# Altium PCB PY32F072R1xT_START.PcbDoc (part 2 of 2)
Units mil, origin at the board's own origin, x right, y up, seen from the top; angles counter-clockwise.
Board outline 1771.65 x 3925.12 mil, 2 copper layers (Top Layer, Bottom Layer), stack 21 mil thick; 156 components, 167 nets, 616 pads, 288 vias.
Unrouted connection lines stored in the file: 5.
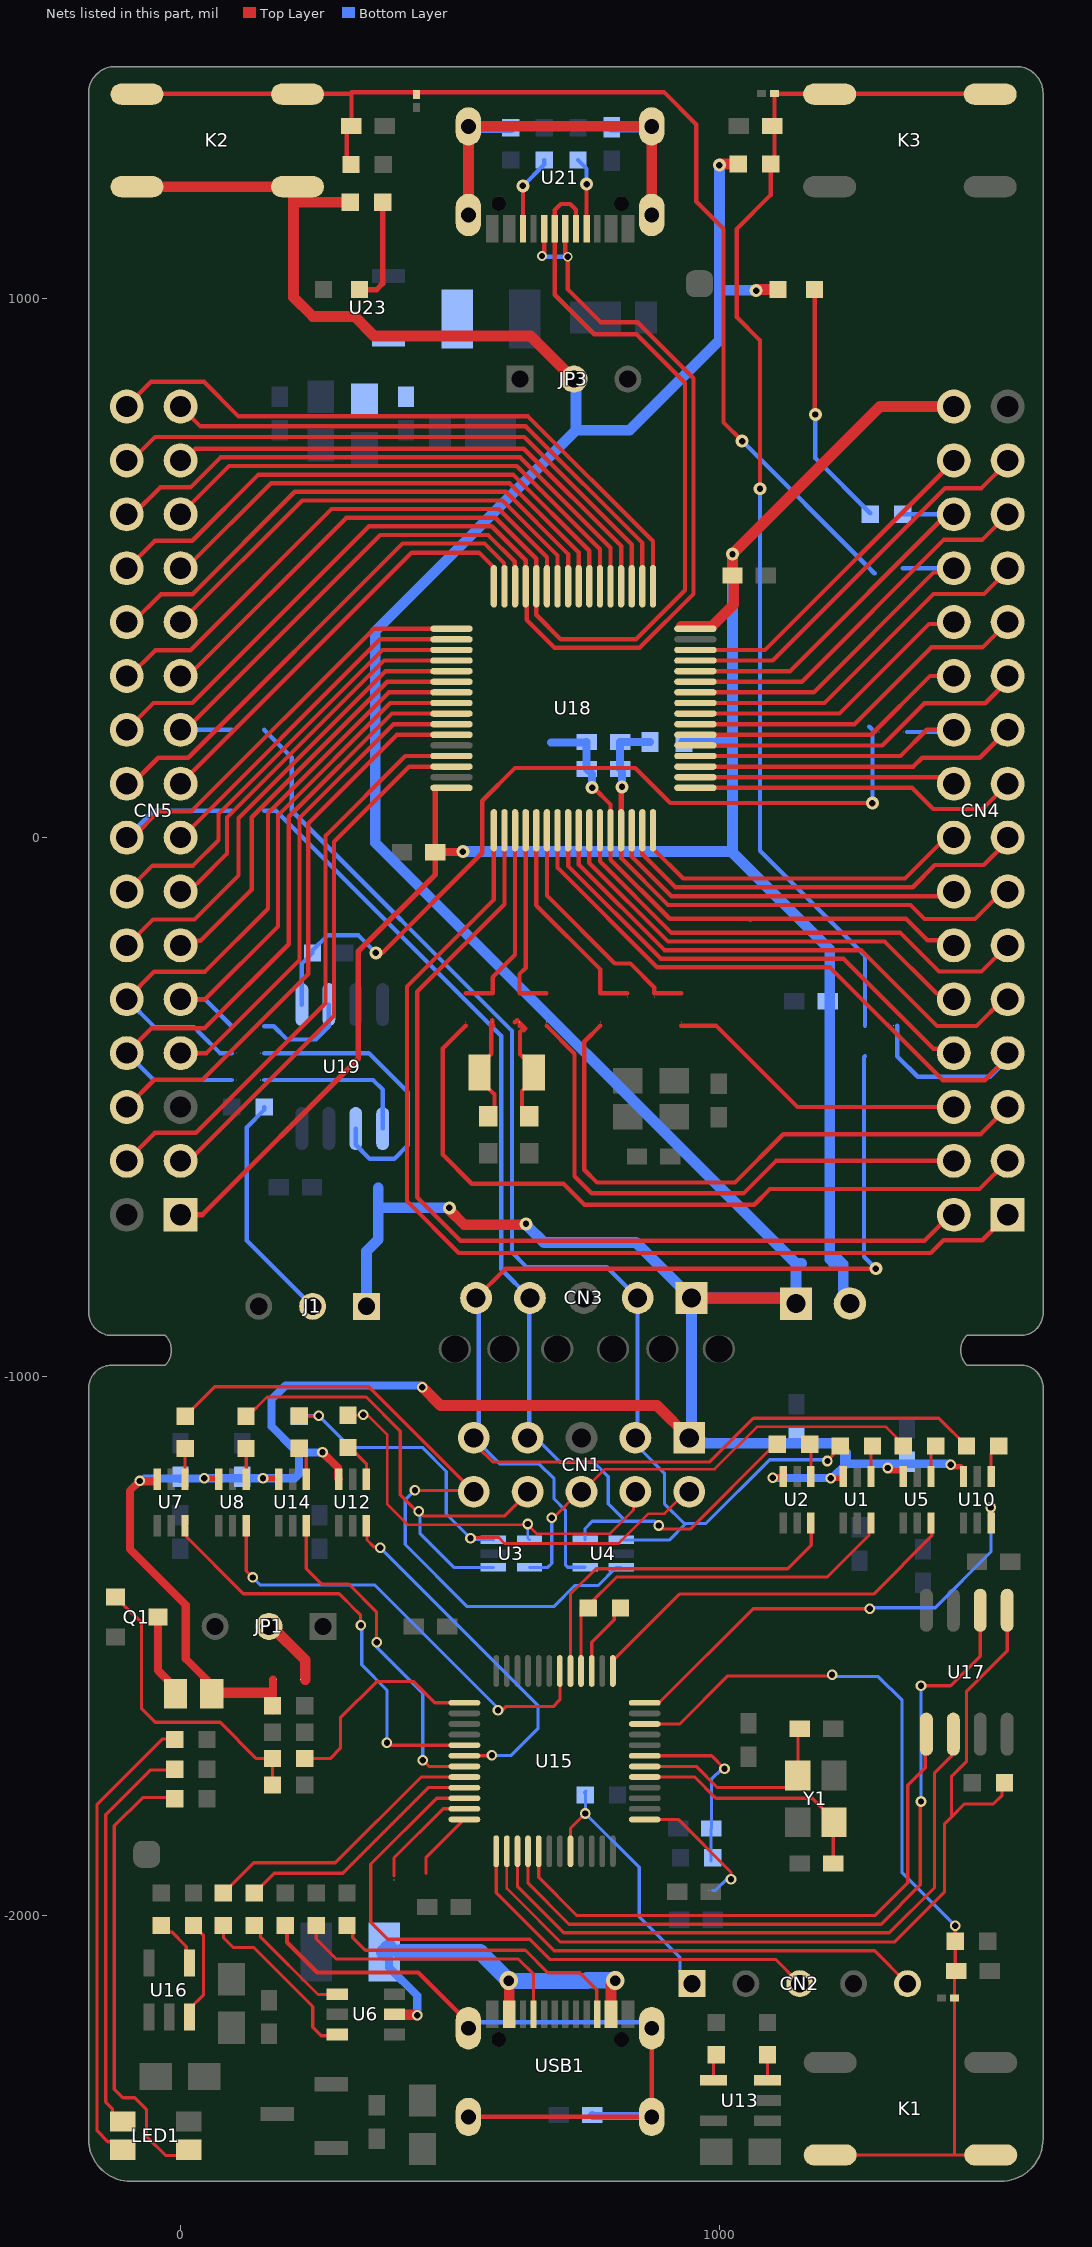
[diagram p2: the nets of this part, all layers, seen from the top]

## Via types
v1: diameter 24, hole 12, Top Layer to Bottom Layer, tented both sides, 117 vias
v2: diameter 19.68, hole 11.81, Top Layer to Bottom Layer, tented both sides, 109 vias
v3: diameter 19.68, hole 11.81, Top Layer to Bottom Layer, 41 vias
v4: diameter 35, hole 20, Top Layer to Bottom Layer, tented both sides, 15 vias
v5: diameter 17.72, hole 11.81, Top Layer to Bottom Layer, tented both sides, 2 vias
v6: diameter 30, hole 15, Top Layer to Bottom Layer, tented both sides, 2 vias
v7: diameter 40, hole 20, Top Layer to Bottom Layer, tented both sides, 2 vias

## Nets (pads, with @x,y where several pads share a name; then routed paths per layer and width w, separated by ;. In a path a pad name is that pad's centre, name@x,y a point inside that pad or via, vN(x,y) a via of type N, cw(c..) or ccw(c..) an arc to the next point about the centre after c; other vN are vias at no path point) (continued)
NetC28_1: C28.1 R42.2 Y3.2 | length 212.9
  Top Layer w8: C28.1@571,-517 582.56,-505.44 582.56,-476.54 554.81,-448.79 Y3.2@554.81,-436 554.81,-423.2 576.75,-401.25 576.75,-351 ; 575.84,-348.25 578.15,-338.54 578.15,-346.4 580.75,-349
NetC29_2: C29.2 R43.2 Y3.1 | length 231
  Top Layer w8: 620.24,-342.82 624.53,-338.53 ; 629,-349 629,-343 640.2,-354.2 636.56,-357.84 ; 636,-351 636,-354.49 629.97,-360.52 629.97,-401.84 634.65,-406.53 638.53,-406.53 646,-414 Y3.1@646,-442 ; C29.2@647,-517 633.5,-503.5 633.5,-470.49 655.2,-448.79 Y3.1@655.2,-436
NetC34_2: C34.2 K3.1 R51.2 R52.1 U20.1 | length 2260.3
  Top Layer w8: v1(1075.24,647.39) 1075.24,922.79 1032.01,966.01 1032.01,1129.47 1095,1192.45 1095,1247.12 R51.2@1095,1250.24 ; R51.2@1098.12,1247.12 1102.3,1251.3 U20.1@1102.3,1381 1102.95,1380.35 1501.9,1380.35 K3.1@1502.55,1379.7
  Bottom Layer w8: v1(1075.24,647.39) 1075.24,-24.52 1270,-219.28 1270,-349
NetC35_2: C35.2 K2.1 R53.1 R54.2 U22.1 | length 2245.4
  Top Layer w8: K2.1@-81,1379.7 -80.35,1380.35 217,1380.35 317,1380.35 C35.2@317,1321 ; R54.2@308.14,1251.87 308.14,1312.14 C35.2@317,1321 ; R54.2@316,1249.26 R54.2@328,1237.26 ; v1(1042.19,735.83) 1007.54,770.49 1007.54,1129.86 956.86,1180.53 956.86,1323.74 897.03,1383.57 317.28,1383.57 317,1383.29 C35.2@317,1321
  Bottom Layer w8: v1(1042.19,735.83) 1275.42,502.61 1276,502.61 1276,502 1287.39,490.61 1288,490.61
NetC38_2: C38.2 C39.2 FUSE2.2 U23.3
NetC40_2: C40.2 R7.1 USB1.1 USB1.2 USB1.3 USB1.4 | length 1406.9
  Top Layer w8: R7.1@194,-2019 197.29,-2022.29 197.29,-2050.13 253.64,-2106.48 440.97,-2106.48 534.12,-2199.63 USB1.1@534.12,-2209.71 ; USB1.3@534.12,-2374.27 USB1.4@874.28,-2374.27 USB1.2@874.28,-2209.71
  Bottom Layer w8: USB1.1@545.04,-2198.79 USB1.2@863.36,-2198.79
  Bottom Layer w15: C40.2@764,-2371 765.64,-2372.64 872.64,-2372.64 USB1.4@874.28,-2374.27
  Bottom Layer w20: USB1.1@534.12,-2209.71 USB1.1@545.04,-2198.79 ; USB1.2@863.36,-2198.79 USB1.2@874.28,-2209.71
NetC41_2: C41.2 R57.2 U21.1 U21.2 U21.3 U21.4 | length 832
  Top Layer w20: U21.2@534.12,1155.52 U21.4@534.12,1320.08 U21.3@874.28,1320.08 U21.1@874.28,1155.52 U21.1@874.28,1163.89
  Bottom Layer w20: U21.4@534.12,1320.08 536.7,1317.5 R57.2@612.5,1317.5 ; C41.2@800,1318.5 872.69,1318.5 U21.3@874.28,1320.08
NetJ1_2: J1.2 R41.1 | length 433.9
  Bottom Layer w8: R41.1@155,-500 155,-505.59 122.74,-537.85 122.74,-747.61 J1.2@245,-869.87
NetLED1_2: LED1.2 R8.1 | length 846.1
  Top Layer w6: R8.1@-11,-1784 -13.33,-1781.67 -70.67,-1781.67 -123,-1834 -123,-2323 -107.2,-2338.8 -85.14,-2338.8 -63.47,-2360.47 -63.47,-2409.84 -27.18,-2446.13 4.08,-2446.13 LED1.2@15.02,-2435.18
NetLED1_3: LED1.3 R5.1 | length 884.3
  Top Layer w6: LED1.3@-126.72,-2435.48 LED1.3@-112.02,-2450.18 ; LED1.3@-107.02,-2435.18 -121.72,-2420.48 -134.91,-2420.48 -155,-2400.39 -155,-1793.66 -34.41,-1673.07 -11.93,-1673.07 R5.1@-11,-1674
NetLED1_4: LED1.4 R4.1 | length 755.1
  Top Layer w6: LED1.4@-114.34,-2395.5 -126.64,-2383.19 -126.64,-2359.26 -139,-2346.91 -139,-1813.66 -55.61,-1730.27 -12.27,-1730.27 R4.1@-11,-1729
NetLED2_VDD*_1: LED2_VDD*.1 R59.1 | length 198.6
  Top Layer w10: LED2_VDD*.1@332,1017 364,1017 375,1028 R59.1@375,1179
NetLED3_PB2_2: LED3_PB2.2 R46.1 | length 460.1
  Top Layer w8: LED3_PB2.2@1176.06,1018.88 1177.06,1017.88 1177.06,788.95 v1@1178.04,787.97
  Bottom Layer w8: v1@1178.04,787.97 1178.04,703.9 R46.1@1280.06,601.88
  other v1: 1178.22,785.23
NetQ1_1: Q1.1 R18.1 R19.2 | length 559
  Top Layer w6: Q1.1@-121,-1409.2 -119.03,-1409.2 -107.28,-1420.94 -107.28,-1422.77 -72.54,-1457.51 -72.54,-1616.66 -47.14,-1642.06 73.45,-1642.06 140.61,-1709.22 R18.1@170.53,-1709.22 ; R19.2@170.52,-1758.12 R18.1@170.52,-1709.23
NetQ1_3: Q1.3 R14.1 | length 166.5
  Top Layer w6: Q1.3@-45.51,-1449.85 Q1.3@-42.26,-1446.6 ; R14.1@-9.46,-1589 R14.1@-9.46,-1583.09
  Top Layer w15: Q1.3@-42.26,-1446.6 -42.26,-1545.72 -9.46,-1578.51 R14.1@-9.46,-1589
NetR1_2: R1.2 USB1.A5 | length 530.2
  Top Layer w6: R1.2@251.49,-2019.01 251.49,-2044.18 288.51,-2081.21 626.58,-2081.21 655.13,-2109.75 USB1.A5@655.13,-2183.97
NetR2_1: R2.1 U1.4 | length 57.9
  Top Layer w6: U1.4@1281.23,-1185.69 1281.23,-1131.98 R2.1@1284.21,-1129
NetR3_1: R3.1 USB1.B5 | length 566
  Top Layer w6: R3.1@309,-2019 319.31,-2029.31 319.31,-2041.66 342.85,-2065.2 640.11,-2065.2 681.66,-2106.76 740.55,-2106.76 772.17,-2138.38 772.17,-2183.18 USB1.B5@773.1,-2184.11
NetR6_1: R6.1 U2.4 | length 57.8
  Top Layer w6: R6.1@1167.06,-1129 1169.8,-1131.73 U2.4@1169.8,-1185.69
NetR9_1: R9.1 U5.4 | length 60.3
  Top Layer w6: U5.4@1392.66,-1185.69 1392.66,-1137.7 R9.1@1401.35,-1129
NetR10_1: R10.1 U6.3 | length 332.9
  Top Layer w6: R10.1@79,-2019 79.77,-2019.77 79.77,-2042.31 97.41,-2059.95 135.8,-2059.95 245.24,-2169.39 245.24,-2208.13 260.63,-2223.52 288.74,-2223.52 U6.3@290.53,-2221.72
NetR11_1: R11.1 U6.1 | length 227.7
  Top Layer w6: R11.1@137.75,-2014 148.15,-2024.4 148.15,-2040.32 255,-2147.17 U6.1@300.97,-2147.17
NetR12_1: R12.1 U7.4 | length 59
  Top Layer w6: R12.1@2.55,-1134 8.14,-1139.59 U7.4@8.14,-1190.69
NetR13_1: R13.1 U8.4 | length 60.8
  Top Layer w6: R13.1@109.94,-1133.98 R13.1@119.82,-1143.86 ; U8.4@121.86,-1190.69 R13.1@121.86,-1143.88
NetR17_1: R17.1 U10.4 | length 62.7
  Top Layer w6: U10.4@1504.08,-1185.69 1504.08,-1143.41 R17.1@1518.49,-1129
NetR21_1: R21.1 U12.4 | length 75.3
  Top Layer w6: R21.1@310.63,-1131.89 314.62,-1131.89 344.71,-1161.97 U12.4@344.71,-1190.69
NetR23_2: R23.2 U13.4 | length 49.6
  Top Layer w6: U13.4@989,-2306.5 989,-2264 R23.2@994,-2259
NetR24_2: R24.2 U13.3 | length 47.5
  Top Layer w6: U13.3@1089,-2306.5 R24.2@1089,-2259
NetR25_1: R25.1 U14.4 | length 62.8
  Top Layer w6: R25.1@220.2,-1133.3 233.28,-1146.38 U14.4@233.28,-1190.69
NetR26_2: R26.2 U15.1 | length 256.3
  Top Layer w6: U15.1@861.32,-1822.27 923.18,-1822.27 1021.46,-1920.55 v3(1021.46,-1933.12)
  Bottom Layer w6: 987.34,-1954.17 992.61,-1954.17 1013.66,-1933.12 v3(1021.46,-1933.12)
NetR28_2: R28.2 U16.4 | length 96.1
  Top Layer w6: R28.2@-36,-2019 -24,-2031 -16.56,-2031 10.5,-2058.06 10.5,-2083 U16.4@16.5,-2089
NetR29_2: R29.2 U16.3 | length 188.5
  Top Layer w6: U16.3@16.5,-2189 16.5,-2174 42.56,-2147.94 42.56,-2038.32 36,-2031.76 36,-2031 R29.2@24,-2019
NetR30_1: R30.1 U15.36 | length 129.6
  Top Layer w6: 455.21,-1922.25 455.21,-1893.74 U15.36@526.68,-1822.27
NetR32_1: R32.1 U15.35 | length 201.4
  Top Layer w6: 395.96,-1926.6 395.96,-1893.62 487,-1802.58 U15.35@526.68,-1802.58
NetR45_1: R45.1 R47.1 U19.1 | length 1545.9
  Top Layer w8: v1(362.54,-213.95) 374.05,-213.95 559.81,-28.19 559.81,68.5 620.39,129.08 843.77,129.08 908.55,64.3 v1@1283.7,64.3
  Bottom Layer w8: U19.1@225,-310 225,-233.86 R45.1@244.57,-214.3 244.57,-209.24 272.31,-181.5 330.09,-181.5 v1(362.54,-213.95) ; 1278.28,205.72 1288,196 1284,192 v1(1284,64)
NetR48_1: R48.1 U19.2 | length 180.8
  Bottom Layer w8: 155,-350 172.74,-350 197.33,-374.59 251.1,-374.59 275,-350.69 U19.2@275,-310
NetR49_2: R49.2 U19.6 | length 543.1
  Bottom Layer w8: 155,-400 349.09,-400 421.85,-472.76 421.85,-570.73 396.64,-595.93 350.72,-595.93 325,-570.21 U19.6@325,-540
NetR50_2: R50.2 U19.5 | length 299.6
  Bottom Layer w8: 155,-450 357.25,-450 375,-467.75 U19.5@375,-540
NetR55_1: R55.1 U21.A5 | length 134.2
  Top Layer w8: U21.A5@753.41,1129.92 v1(753.41,1212.98)
  Bottom Layer w8: R55.1@737.5,1257.5 753.41,1241.59 v1(753.41,1212.98)
NetR56_2: R56.2 U21.B5 | length 144
  Top Layer w8: U21.B5@635.3,1129.92 v1(635.3,1209.54)
  Bottom Layer w8: v1(635.3,1209.54) 675,1249.24 R56.2@675,1257.5
NRST: CN4.7 R39.2 R52.2 U18.7 | length 1395.9
  Top Layer w8: U18.7@699.47,13.63 699.47,-55.7 884.62,-240.85 1205.25,-240.85 1414.65,-450.25 1492.3,-450.25 1535,-407.55 CN4.7@1535,-400
  Bottom Layer w8: 1330,-349 1330,-406 1368,-444 1502,-444 1535,-411 CN4.7@1535,-400
OSC32_IN: R42.1 R61.1 U18.3 | length 369.9
  Top Layer w8: 529,-289 579,-289 579,-259.23 620.73,-217.5 U18.3@620.73,13.63
OSC32_OUT: R43.1 R62.1 U18.4 | length 357.4
  Top Layer w8: U18.4@640.42,13.63 640.42,-241.94 629,-253.36 629,-289 679,-289
OSC_IN: R36.2 R63.1 U18.5 | length 401.9
  Top Layer w8: U18.5@660.1,13.63 660.1,-125.78 779,-244.68 779,-289 829,-289
OSC_OUT: R40.2 R64.1 U18.6 | length 452
  Top Layer w8: U18.6@679.79,13.63 679.79,-107.68 805.84,-233.73 834.64,-233.73 879,-278.09 879,-289 929,-289
PA0: CN4.14 U18.14 | length 680.8
  Top Layer w8: U18.14@837.27,13.63 837.27,-35.11 911.16,-109 1426,-109 CN4.14@1435,-100
PA1: CN4.15 U18.15 | length 789.8
  Top Layer w8: U18.15@856.95,13.63 856.95,-30.82 918.17,-92.04 1358.59,-92.04 1399.62,-51.01 1490.52,-51.01 1535,-6.53 CN4.15@1535,0
PA2: CN4.16 U18.16 | length 646.7
  Top Layer w8: U18.16@876.64,13.63 876.64,-19.96 932.72,-76.04 1344.52,-76.04 1420.56,0 CN4.16@1435,0
PA3: CN4.17 U18.17 | length 615.5
  Top Layer w8: U18.17@955.37,92.36 1357.49,92.36 1396.91,52.94 1487.94,52.94 CN4.17@1535,100
PA4: CN4.20 R47.2 U18.20 | length 588.3
  Top Layer w8: U18.20@955.37,151.42 1336.28,151.42 1384.86,200 CN4.20@1435,200
  Bottom Layer w8: 1348.11,196.11 1431.11,196.11 CN4.20@1435,200
PA5: CN4.21 U18.21 | length 638.3
  Top Layer w8: U18.21@955.37,171.1 1302.1,171.1 1380.38,249.38 1493.38,249.38 1535,291 CN4.21@1535,300
PA6: CN4.22 U18.22 | length 524.9
  Top Layer w8: U18.22@955.37,190.79 1281.79,190.79 1391,300 CN4.22@1435,300
PA7: CN4.23 U18.23 | length 658.1
  Top Layer w8: U18.23@955.37,210.47 1250.53,210.47 1393.07,353.02 1487.98,353.02 CN4.23@1535,400
PA8: CN5.24 U18.41 | length 1027
  Top Layer w8: CN5.24@-100,400 -88.14,400 -36.4,451.74 21.74,451.74 211.7,641.7 603.8,641.7 719.16,526.34 U18.41@719.16,466.37
PA9: CN5.23 U18.42 | length 892.4
  Top Layer w8: CN5.23@0,400 225.7,625.7 597.17,625.7 699.47,523.4 U18.42@699.47,466.37
PA10: CN5.22 U18.43 | length 999.1
  Top Layer w8: CN5.22@-100,300 -94.81,300 -47.29,347.52 17.68,347.52 279.86,609.7 590.54,609.7 679.79,520.46 U18.43@679.79,466.37
PA11: CN5.21 U18.44 U21.A7 U21.B7 | length 2185.1
  Top Layer w8: CN5.21@0,300 13.93,300 307.63,593.7 583.91,593.7 660.1,517.52 660.1,413.43 705.29,368.24 845.24,368.24 936,459 936,844.16 845.82,934.34 767.57,934.34 694.36,1007.55 U21.A7@694.36,1129.92 694.36,1164.7 705.63,1175.98 722.99,1175.98 733.73,1165.24 U21.B7@733.73,1129.92
PA12: CN5.20 U18.45 U21.A6 U21.B6 | length 2329.4
  Top Layer w8: CN5.20@-100,200 -100,210 -90,210 -50.23,249.77 21.4,249.77 349.34,577.7 577.29,577.7 640.42,514.57 U18.45@640.42,466.37 641.15,465.64 641.15,429.48 642.19,428.44 642.19,404.06 694.02,352.24 851.87,352.24 952,452.37 952,852.58 848.38,956.2 779.98,956.2 718.19,1017.99 v5(718.19,1078.14) 714.04,1082.3 U21.A6@714.04,1129.92 ; v5(670.65,1079.43) 674.67,1083.45 U21.B6@674.67,1129.92
  Bottom Layer w8: v5(670.65,1079.43) 672.06,1078.01 672.2,1078.14 v5(718.19,1078.14)
PA13: CN5.19 R37.2 U18.46 | length 931.6
  Top Layer w8: CN5.19@0,200 8.86,200 370.57,561.7 570.66,561.7 620,512.36 620,467.1 U18.46@620.73,466.37
  Bottom Layer w8: CN5.19@0,200 95,200
PA14: CN5.16 R38.2 U18.49 | length 978.9
  Top Layer w8: CN5.16@-100,0 -88.98,0 -39.89,49.09 20.28,49.09 358.83,387.64 U18.49@502.63,387.64
  Bottom Layer w8: CN5.16@-100,0 -50,50 95,50
PA15: CN5.15 U18.50 | length 655
  Top Layer w8: CN5.15@0,0 2.31,0 370.26,367.95 U18.50@502.63,367.95
PB0: CN4.26 R53.2 U18.26 | length 670.1
  Top Layer w8: U18.26@955.37,269.53 1174.9,269.53 1397.43,492.06 1427.06,492.06 CN4.26@1435,500
  Bottom Layer w8: 1340,500 CN4.26@1435,500
PB1: CN4.27 U18.27 | length 708.4
  Top Layer w8: U18.27@955.37,289.21 1153.06,289.21 1416.85,553 1488,553 CN4.27@1535,600
PB2: CN4.28 R46.2 U18.28 | length 701.6
  Top Layer w8: U18.28@955.37,308.9 1130.9,308.9 1422,600 CN4.28@1435,600
  Bottom Layer w8: R46.2@1340,600 CN4.28@1435,600 CN4.28@1430.5,595.5
PB3: CN5.10 R49.1 U18.55 | length 1178.9
  Top Layer w8: CN5.10@-100,-300 -48.79,-248.79 45.35,-248.79 161.97,-132.17 161.97,45.25 386.26,269.53 U18.55@502.63,269.53
  Bottom Layer w8: CN5.10@-100,-300 -48.3,-351.7 24.73,-351.7 37.88,-364.85 73.03,-400 95,-400
PB4: CN5.9 R48.2 U18.56 | length 966.8
  Top Layer w8: CN5.9@0,-300 45.49,-300 180.65,-164.85 180.65,41.29 389.2,249.84 U18.56@502.63,249.84
  Bottom Layer w8: CN5.9@0,-300 45,-300 95,-350
PB5: CN5.8 R50.1 U18.57 | length 1217.9
  Top Layer w8: CN5.8@-100,-400 -54,-354 44.53,-354 200.52,-198.01 200.52,38.54 392.14,230.16 U18.57@502.63,230.16
  Bottom Layer w8: CN5.8@-100,-400 -50,-450 95,-450
PB6: CN5.7 U18.58 | length 909.8
  Top Layer w8: CN5.7@0,-400 48.07,-400 220.71,-227.35 220.71,36.1 395.08,210.47 U18.58@502.63,210.47
PB7: CN5.6 U18.59 | length 1052.4
  Top Layer w8: CN5.6@-100,-500 -99.38,-500 -48.88,-449.5 40.36,-449.5 236.71,-253.15 236.71,26.2 401.3,190.79 U18.59@502.63,190.79
PB8: CN5.4 U18.61 | length 1095.8
  Top Layer w8: CN5.4@-100,-600 -48,-548 28.03,-548 268.71,-307.32 268.71,3.2 416.94,151.42 U18.61@502.63,151.42
PB9: CN5.3 U18.62 | length 994.7
  Top Layer w8: CN5.3@0,-600 14.88,-600 30.02,-584.86 30.38,-584.86 284.71,-330.53 284.71,-7.86 424.31,131.73 U18.62@502.63,131.73
PB10: CN4.29 U18.29 | length 735.1
  Top Layer w8: U18.29@955.37,328.58 1098.94,328.58 1418.92,648.56 1486.32,648.56 1535,697.24 CN4.29@1535,700
PB11: CN4.30 U18.30 | length 626.2
  Top Layer w8: U18.30@955.37,348.27 1084.69,348.27 1435,698.58 CN4.30@1435,700
PB12: CN5.32 U18.33 | length 1202.4
  Top Layer w8: CN5.32@-100,800 -100,801.08 -55.15,845.93 43.24,845.93 107.35,781.81 644.71,781.81 876.64,549.88 U18.33@876.64,466.37
PB13: CN5.31 U18.34 | length 1042.3
  Top Layer w8: CN5.31@0,800 36.75,763.25 640.64,763.25 856.95,546.94 U18.34@856.95,466.37
PB14: CN5.30 U18.35 | length 1115.5
  Top Layer w8: CN5.30@-100,700 -91.25,700 -47.76,743.5 328.5,743.5 637.77,743.5 837.27,544 U18.35@837.27,466.37
PB15: CN5.29 U18.36 | length 978.4
  Top Layer w8: CN5.29@0,700 2.82,697.18 27.34,721.7 636.93,721.7 817.58,541.06 U18.36@817.58,466.37
PC0: CN4.8 U18.8 | length 926.1
  Top Layer w8: U18.8@719.16,13.63 719.16,-52.76 891.25,-224.85 1230.24,-224.85 1397.44,-392.05 1427.05,-392.05 CN4.8@1435,-400
PC1: CN4.9 U18.9 | length 1004.3
  Top Layer w8: U18.9@738.84,13.63 738.84,-49.82 897.88,-208.85 1262.96,-208.85 1403.7,-349.59 1477.03,-349.59 1526.62,-300 CN4.9@1535,-300
PC2: CN4.10 U18.10 | length 841.8
  Top Layer w8: U18.10@758.53,13.63 758.53,-46.88 904.5,-192.85 1306.51,-192.85 1403.14,-289.48 1424.48,-289.48 CN4.10@1435,-300
PC3: CN4.11 U18.11 | length 919.3
  Top Layer w8: U18.11@778.21,13.63 778.21,-43.93 911.13,-176.85 1335.81,-176.85 1407.58,-248.63 1486.37,-248.63 CN4.11@1535,-200
PC4: CN4.24 U18.24 | length 550
  Top Layer w8: U18.24@955.37,230.16 1222.76,230.16 1389.11,396.5 1431.5,396.5 CN4.24@1435,400
PC5: CN4.25 U18.25 | length 685.6
  Top Layer w8: U18.25@955.37,249.84 1194.99,249.84 1397.26,452.11 1491.12,452.11 1535,495.99 CN4.25@1535,500
PC6: CN5.28 U18.37 | length 1082.8
  Top Layer w8: CN5.28@-100,600 -87.96,600 -38.01,649.94 18.24,649.94 74.01,705.7 630.31,705.7 797.9,538.11 U18.37@797.9,466.37
PC7: CN5.27 U18.38 | length 948.2
  Top Layer w8: CN5.27@0,600 0.6,600.6 89.7,689.7 623.68,689.7 778.21,535.17 U18.38@778.21,466.37
PC8: CN5.26 U18.39 | length 1054.9
  Top Layer w8: CN5.26@-100,500 -98.8,500 -47.78,551.03 21.55,551.03 144.23,673.7 617.05,673.7 758.53,532.23 U18.39@758.53,466.37
PC9: CN5.25 U18.40 | length 920.3
  Top Layer w8: CN5.25@0,500 4.91,504.91 14.76,504.91 167.56,657.7 610.42,657.7 738.84,529.29 U18.40@738.84,466.37
PC10: CN5.14 U18.51 | length 816.8
  Top Layer w8: CN5.14@-100,-100 -52,-52 22.93,-52 70.1,-4.83 70.1,43.88 374.49,348.27 U18.51@502.63,348.27
PC11: CN5.13 U18.52 | length 719.4
  Top Layer w8: CN5.13@0,-100 14.88,-100 29.69,-85.19 30.7,-85.19 86.1,-29.79 86.1,37.25 377.43,328.58 U18.52@502.63,328.58
PC12: CN5.12 U18.53 | length 875.6
  Top Layer w8: CN5.12@-100,-200 -99.05,-200 -51.05,-152 25.57,-152 107.48,-70.09 107.48,36 380.37,308.9 U18.53@502.63,308.9
PC13: CN4.2 U18.2 | length 1797.9
  Top Layer w8: U18.2@601.05,13.63 601.05,-123.76 439,-285.81 439,-667.78 519.54,-748.33 1380.74,-748.33 1429.07,-700 CN4.2@1435,-700
PC14: CN4.3 R61.2 | length 1377.8
  Top Layer w8: 529,-349 486.47,-391.53 486.47,-588.43 540.35,-642.3 710.53,-642.3 749.57,-681.34 1064.66,-681.34 1093.65,-652.35 1482.65,-652.35 CN4.3@1535,-600
PC15: CN4.4 R62.2 | length 1043.1
  Top Layer w8: 679,-349 731,-401 731,-628.35 762.93,-660.27 1044.73,-660.27 1105,-600 CN4.4@1435,-600
PF0: CN4.5 R63.2 | length 1133.5
  Top Layer w8: 779,-349 749.14,-378.86 749.14,-616.36 772.93,-640.15 1028.85,-640.15 1118.46,-550.54 1484.46,-550.54 CN4.5@1535,-500
PF1: CN4.6 R64.2 | length 568.5
  Top Layer w8: 929,-349 993.75,-349 1144.75,-500 CN4.6@1435,-500
PF3: CN4.18 U18.18 | length 484.6
  Top Layer w8: U18.18@955.37,112.05 1408.07,112.05 1420.12,100 CN4.18@1435,100
PF4: CN4.19 U18.19 | length 607.9
  Top Layer w8: U18.19@955.37,131.73 1359.86,131.73 1376.33,148.2 1483.2,148.2 CN4.19@1535,200
PF5: CN5.18 U18.47 | length 943.3
  Top Layer w8: CN5.18@-100,100 -89.69,100 -41.43,148.26 14.18,148.26 411.63,545.7 564.03,545.7 600.32,509.42 600.32,467.1 U18.47@601.05,466.37
PF6: CN5.17 U18.48 | length 805.3
  Top Layer w8: CN5.17@0,100 428.94,528.94 553.57,528.94 581.3,501.21 581.3,466.43 U18.48@581.36,466.37
PF7: CN5.11 U18.54 | length 784
  Top Layer w8: CN5.11@0,-200 8.5,-191.5 37.02,-191.5 132.02,-96.5 132.02,37.91 383.31,289.21 U18.54@502.63,289.21
PF9: CN4.1 U18.1 | length 1939.4
  Top Layer w8: U18.1@581.36,13.63 581.36,-115.1 420,-276.46 420,-674.66 516.27,-770.93 1392.27,-770.93 1415.92,-747.27 1487.73,-747.27 CN4.1@1535,-700
PYLK_BOOT0: CN2.1 R27.1 U15.44 | length 522.7
  Top Layer w6: U15.44@723.53,-1881.32 723.53,-1838.93 v2(751.21,-1811.25)
  Bottom Layer w6: R27.1@752.26,-1769.6 749.49,-1772.37 751.21,-1774.1 v2(751.21,-1811.25) 851,-1911.04 851,-2003 926.96,-2078.96 926.96,-2104.96 CN2.1@949,-2127
PYLK_KEY: C5.2 K1.2 R15.1 U11.1 U15.10 | length 1779.6
  Top Layer w6: U15.10@861.32,-1645.1 926.14,-1645.1 1015.44,-1555.8 1207.2,-1555.8 v2(1209,-1554) ; K1.2@1205.55,-2445 1467.3,-2445 1482.51,-2445 K1.2@1468.02,-2459.49 ; C5.2@1436.3,-2106.3 U11.1@1436.3,-2154 1436.3,-2445 K1.2@1503.55,-2445 ; v2(1437.39,-2019.46) 1437.76,-2019.83 R15.1@1437.76,-2048.15 C5.2@1437.76,-2101.51
  Bottom Layer w6: v2(1209,-1554) 1212.06,-1557.06 1221.62,-1557.06 1221.69,-1557.12 1294.92,-1557.12 1339,-1601.2 1339,-1921.07 v2(1437.39,-2019.46)
PYLK_NRST: C23.2 R35.1 U15.7 | length 341.9
  Top Layer w6: U15.7@861.32,-1704.16 985.36,-1704.16 v2(1009.4,-1728.2)
  Bottom Layer w6: R35.1@984.12,-1899 984.12,-1840 C23.2@985.12,-1839 985.12,-1748 1004.92,-1728.2 v2(1009.4,-1728.2)
PYLK_OSCIN: C18.2 U15.5 Y1.3 | length 465.6
  Top Layer w6: U15.5@861.32,-1743.53 954.05,-1743.53 993.42,-1782.9 1172.11,-1782.9 1212.59,-1823.37 Y1.3@1212.59,-1827.31 1211.12,-1828.78 C18.2@1211.12,-1904
PYLK_OSCOUT: C24.2 U15.6 Y1.1 | length 399.8
  Top Layer w6: U15.6@861.32,-1723.84 956.99,-1723.84 996.36,-1763.21 1126.03,-1763.21 1145.66,-1743.59 Y1.1@1145.66,-1740.69 1145.66,-1657.46 C24.2@1149.12,-1654
PYLK_SPI_CS: R34.1 U15.38 U17.1 | length 1667.6
  Top Layer w5: U15.38@605.42,-1881.32 605.42,-1950.38 666.66,-2011.62
  Top Layer w6: 666.66,-2011.62 704.95,-2049.91 1324.51,-2049.91 1417.88,-1956.53 1417.88,-1830.12 1430.77,-1817.23 ; R34.1@1529,-1754 1524.62,-1758.38 1524.62,-1777.31 1508.36,-1793.58 1454.42,-1793.58 1430.77,-1817.23 ; U17.1@1534,-1434 1534,-1509 1458.69,-1584.31 1458.69,-1713.99 1430.77,-1741.91 1430.77,-1817.23
PYLK_SPI_MISO: U15.40 U17.2 | length 1437.2
  Top Layer w6: U15.40@644.79,-1881.32 644.79,-1940.7 720.8,-2016.7 1300,-2016.7 1372.9,-1943.8 1372.9,-1790.1 v2(1374,-1789) ; v2(1374,-1574) 1429,-1574 1484,-1519 U17.2@1484,-1434
  Bottom Layer w6: v2(1374,-1789) v2(1374,-1574)
PYLK_SPI_MOSI: U15.41 U17.5 | length 1077.9
  Top Layer w6: U15.41@664.47,-1881.32 664.47,-1929.51 735.66,-2000.7 1288.42,-2000.7 1349.53,-1939.59 1349.53,-1758.91 1382.13,-1726.31 1382.13,-1665.87 U17.5@1384,-1664
PYLK_SPI_SCK: U15.39 U17.6 | length 1208.9
  Top Layer w6: U15.39@625.1,-1881.32 625.1,-1946.64 685.32,-2006.86 711.17,-2032.7 1315.07,-2032.7 1399.21,-1948.56 1399.21,-1735.94 1430.94,-1704.21 1430.94,-1667.06 U17.6@1434,-1664
SWD_SCK: CN2.5 U15.37 | length 910.1
  Top Layer w6: U15.37@585.73,-1881.32 585.73,-1958.25 693.48,-2066 1288,-2066 CN2.5@1349,-2127
SWD_SDA: CN2.3 U15.34 | length 1175.6
  Top Layer w6: U15.34@526.68,-1782.9 475.11,-1782.9 353.05,-1904.96 353.05,-2013.29 384.57,-2044.8 647.75,-2044.8 684.95,-2082 1104,-2082 CN2.3@1149,-2127
T_RESET: CN1.9 CN3.5 R17.2 R39.1 U4.4 | length 2794
  Top Layer w6: CN1.9@551.78,-1131.22 579.2,-1158.64 981.91,-1158.64 1062.99,-1077.56 1407.06,-1077.56 R17.2@1458.49,-1129
  Top Layer w8: CN3.5@548.26,-854.44 602.65,-800.05 v1(1290.47,-800.05)
  Bottom Layer w6: CN1.9@544,-1114 592.22,-1162.22 665.02,-1162.22 693.1,-1190.31 693.1,-1227.58 714.15,-1248.63 714.15,-1349.69 718.61,-1354.15 750.09,-1354.15 U4.4@750.54,-1354.59
  Bottom Layer w8: CN1.9@544,-1114 553.04,-1104.96 553.04,-859.22 CN3.5@548.26,-854.44 ; 1270,-406 1268.46,-407.54 1268.46,-778.04 v1(1290.47,-800.05)
T_RESETa: U10.3 U15.12 | length 870.1
  Top Layer w6: U15.12@861.32,-1605.73 887.79,-1605.73 1062.47,-1431.04 1150.53,-1431.04 v2(1278.91,-1431.04) ; v2(1503.82,-1243.3) 1504.08,-1243.56 U10.3@1504.08,-1272.31
  Bottom Layer w6: v2(1278.91,-1431.04) 1280.65,-1429.3 1400.4,-1429.3 1503.82,-1325.89 v2(1503.82,-1243.3)
T_RTCK_DTRa: U5.3 U15.13 | length 731.2
  Top Layer w6: U15.13@802.27,-1546.68 802.27,-1527.43 925.7,-1404 1285.99,-1404 1394.18,-1295.81 1394.18,-1273.84 U5.3@1392.66,-1272.31
T_RTCK_VCP_DTR: CN1.6 R9.2 U3.5 | length 868.3
  Top Layer w5: v2(688.81,-1262.33) 692.24,-1262.33 740.57,-1214 CN1.6@744,-1214 745.63,-1214 787.49,-1172.14 990.73,-1172.14 1069.3,-1093.56 1308.98,-1093.56 1329.35,-1113.93 1329.35,-1117 R9.2@1341.35,-1129
  Bottom Layer w6: U3.5@647.46,-1354.59 681.51,-1354.59 688.81,-1347.29 v2(688.81,-1262.33)
T_TCK_SWCLK: CN1.7 CN3.4 R6.2 R38.1 U4.5 | length 2109
  Top Layer w6: CN1.7@649,-1104 CN1.7@650.35,-1102.65 ; v2(887.5,-1276.68) 894.14,-1283.31 945.96,-1283.31 1100.28,-1129 R6.2@1107.06,-1129
  Bottom Layer w6: CN1.7@651.5,-1106.5 704.47,-1159.47 766.65,-1159.47 793.6,-1186.43 793.6,-1236.46 826.14,-1269 ; U4.5@750.54,-1303.41 750.54,-1282.46 764,-1269 826.14,-1269 ; v2(887.5,-1276.68) 879.82,-1269 826.14,-1269
  Bottom Layer w8: 155,50 176.97,50 594.97,-368 594.97,-801.14 CN3.4@648.26,-854.44 646.79,-855.9 646.79,-1111.21 CN1.7@644,-1114
T_TCK_SWCLKa: U2.3 U15.17 | length 668.1
  Top Layer w5: U15.17@723.53,-1546.68 723.53,-1404.24 770.77,-1357
  Top Layer w6: 770.77,-1357 876.62,-1357 1126.43,-1357 1170.41,-1313.02 1170.41,-1272.92 U2.3@1169.8,-1272.31
T_TDI_VCP_TX: CN1.4 R21.2 U3.4 | length 783.1
  Top Layer w5: R21.2@310.63,-1071.89 346.9,-1071.89 383.54,-1108.52 383.54,-1237.38 421.29,-1275.14 v2@644,-1275.14 ; R21.2@310.63,-1068.89 R21.2@312.13,-1070.39 ; v2@644.02,-1275.14 660.78,-1291.89 796.76,-1291.89 840.56,-1248.1 840.56,-1217.44 CN1.4@844,-1214
  Bottom Layer w5: v2@644.06,-1274.06 644.06,-1300 U3.4@647.46,-1303.41
  other v2: 644,-1274
  other v3: 338.96,-1071.02
T_TDI_VCP_TXa: U12.3 U15.30 | length 672
  Top Layer w6: U12.3@344.71,-1277.31 345.93,-1278.53 345.93,-1303.63 358.24,-1315.94 368.56,-1315.94 v2(370.31,-1317.69) ; U15.30@526.68,-1704.16 577.02,-1704.16 v2(577.76,-1703.42)
  Bottom Layer w6: v2(370.31,-1317.69) 663.09,-1610.47 663.09,-1654.23 629.71,-1687.62 613.91,-1703.42 v2(577.76,-1703.42)
T_TDO_SWO: CN1.10 R12.2 U4.3 | length 1333.3
  Top Layer w6: R12.2@8.66,-1073.92 63.47,-1019.1 349.1,-1019.1 CN1.10@537.51,-1207.51 ; v2(434.87,-1211.25) 435.54,-1211.92 533.1,-1211.92 CN1.10@537.51,-1207.51 ; CN1.10@544,-1214 CN1.10@537.51,-1207.51
  Bottom Layer w6: v2(434.87,-1211.25) 416.83,-1229.28 416.83,-1311.92 532.06,-1427.14 692.29,-1427.14 731.42,-1388.01 775.45,-1388.01 808.88,-1354.59 U4.3@817.46,-1354.59 U4.3@815.15,-1356.9
T_TDO_SWOa: U7.3 U15.29 | length 807.7
  Top Layer w6: U7.3@8.14,-1277.31 8.14,-1295.14 116.46,-1403.46 294.08,-1403.46 300.63,-1410 301.01,-1410 318,-1426.99 318,-1427.37 333.93,-1443.3 333.93,-1461.31 v2(334.62,-1462) ; v2(382.88,-1679.67) 387.68,-1684.47 470.55,-1684.47 U15.29@526.68,-1684.47
  Bottom Layer w6: v2(334.62,-1462) 335.95,-1463.32 335.95,-1535.07 382.88,-1582 v2(382.88,-1679.67)
T_TMS_SWDIO: CN1.3 CN3.2 R2.2 R37.1 U4.1 | length 2355.5
  Top Layer w6: CN1.3@848.37,-1127.81 CN1.3@854.56,-1134 ; v2@1200.62,-1155.69 1211.21,-1145.1 1211.21,-1142 R2.2@1224.21,-1129
  Bottom Layer w6: U4.1@817.77,-1303.71 906.45,-1303.71 937.1,-1273.06 ; CN1.3@852.59,-1134.3 897.86,-1179.58 897.86,-1236.11 934.81,-1273.06 937.1,-1273.06 ; v2(1200.43,-1156.93) 1198.25,-1154.75 1093.29,-1154.75 974.98,-1273.06 937.1,-1273.06
  Bottom Layer w8: 155,200 206.3,148.7 206.3,49.83 614.84,-358.71 614.84,-769.54 642.16,-796.85 790.67,-796.85 CN3.2@848.26,-854.44 848,-854.7 848,-1110 CN1.3@844,-1114
T_TMS_SWDIOa: R31.1 U1.3 U15.16 | length 723.8
  Top Layer w6: U15.16@743.21,-1546.68 R31.1@743.21,-1426.63 ; R31.1@756.46,-1429.63 756.46,-1425.01 809.12,-1372.35 865.7,-1372.35 1200.22,-1372.35 1277.34,-1295.23 1277.34,-1276.2 U1.3@1281.23,-1272.31
T_TMS_SWDIOa_IN: R31.2 U15.15 | length 143.2
  Top Layer w6: U15.15@762.9,-1546.68 762.9,-1493.36 804.82,-1451.44 R31.2@804.82,-1420.84
T_TRST_RTSa: U8.3 U15.18 | length 840.3
  Top Layer w6: U8.3@121.86,-1277.31 121.86,-1361.14 v2(133.82,-1373.1) ; v2(588.92,-1619.65) 592.83,-1623.56 603.54,-1612.84 691.39,-1612.84 703.84,-1600.4 U15.18@703.84,-1546.68
  Bottom Layer w6: v2(133.82,-1373.1) 147.81,-1387.09 360.65,-1387.09 588.92,-1615.36 v2(588.92,-1619.65)
T_TRST_VCP_RTS: CN1.8 R13.2 U3.1 | length 935
  Top Layer w6: R13.2@121.3,-1073.9 124.54,-1073.9 160.24,-1038.2 344.25,-1038.2 407.58,-1101.53 407.58,-1219.44 438.4,-1250.27 v2(441.86,-1250.27) 450.6,-1259 601.67,-1259 649,-1211.67 CN1.8@649,-1204
  Bottom Layer w6: v2(441.86,-1250.27) 444,-1252.4 444,-1291.4 507.19,-1354.59 U3.1@580.54,-1354.59
T_VCP_RX: CN1.2 R22.1 R25.2 U3.3 | length 1000.9
  Top Layer w5: v2(537.97,-1300.26) 539.23,-1299 590.42,-1299 601.45,-1310.03 812.91,-1310.03 868.3,-1254.64 898.36,-1254.64 CN1.2@949,-1204
  Top Layer w6: R25.2@220.2,-1073.3 255.7,-1073.3 v3(256,-1073) ; R25.2@220.2,-1062.15 R25.2@220.32,-1062.03
  Bottom Layer w6: R22.1@220,-1074 221,-1073 v3(256,-1073) 314.72,-1131.72 448.26,-1131.72 493.05,-1176.5 493.05,-1255.34 v2(537.97,-1300.26) 537.23,-1301 537.23,-1302.23 579.36,-1302.23 U3.3@580.54,-1303.41
T_VCP_RXa: U14.3 U15.31 | length 636
  Top Layer w6: U14.3@233.28,-1277.31 233.28,-1356.71 262.27,-1385.7 312.54,-1385.7 363.4,-1436.57 363.4,-1492.62 v2(364,-1493.22) ; v2(449.4,-1712.25) 460.99,-1723.84 U15.31@526.68,-1723.84
  Bottom Layer w6: v2(364,-1493.22) 364,-1502.58 449.4,-1587.98 v2(449.4,-1712.25)
TVDD: C11.2 C12.2 C13.2 C14.2 CN1.1 CN3.1 J1.1 JP2.1 JP3.2 K2.2 LED3_PB2.1 R14.2 R16.2 R22.2 R33.2 R44.1 R51.1 R58.1 R59.2 U1.6 U2.6 U5.6 U7.6 U8.6 U10.6 U12.6 U14.6 | length 8646.3
  Top Layer w6: U8.6@70.67,-1190.69 U8.6@73.56,-1187.8 ; U14.6@182.1,-1190.69 U14.6@184.99,-1187.8
  Top Layer w10: v2(44,-1189) 68.98,-1189 U8.6@70.67,-1190.69 ; v3@154,-1189 180.41,-1189 U14.6@182.1,-1190.69 ; v3(1206.88,-1188.91) 1228.07,-1188.91 1228.16,-1189 1230.05,-1187.11 U1.6@1230.05,-1185.69 ; v2(1312.29,-1169.94) 1317.61,-1175.26 1341.47,-1175.26 U5.6@1341.47,-1185.69 ; v2@1437.68,-1167.9 1447.91,-1167.9 1452.9,-1172.9 U10.6@1452.9,-1185.69
  Top Layer w12: v2@1099.9,-1187.1 U2.6@1118.01,-1187.1
  Top Layer w15: v2(-76,-1194) -94.34,-1212.34 -94.34,-1320.4 9.53,-1424.27 9.53,-1524.05 49.52,-1564.04 49.52,-1581.05 R14.2@57.46,-1589 R14.2@59.24,-1587.22 ; v2@-75.37,-1194.63 U7.6@-43.65,-1194.63 ; 167.07,-1587.22 171.08,-1591.23 ; R16.2@171.08,-1619.98 171.08,-1591.23 ; 171.08,-1562.48 171.08,-1591.23 ; v3(263.28,-1140.95) 291.84,-1169.51 291.84,-1189 U12.6@293.53,-1190.69 ; v2(1099,-1188) v2@1099.9,-1187.1
  Top Layer w20: K2.2@-81,1208 K2.2@212.32,1208 ; R14.2@59.24,-1587.22 167.07,-1587.22 ; K2.2@217,1208 209.49,1200.49 209.49,1175 ; R59.2@315,1179 213.49,1179 209.49,1175 ; v3(448.35,-1019.84) 482.41,-1053.9 883.9,-1053.9 CN1.1@944,-1114 ; v1(498.87,-687.15) 498.87,-691.09 526.44,-718.66 636.51,-718.66 637.41,-717.77 v1@639.15,-717.77 ; JP3.2@729.27,851 649.38,930.9 359.03,930.9 322.55,967.38 245.04,967.38 209.49,1002.93 209.49,1175 ; CN3.1@948.26,-854.44 1131.56,-854.44 JP2.1@1142,-864.87 ; v1(1000,1248) 1002.24,1250.24 R51.1@1035,1250.24 ; v1(1068,1015) 1070,1017 LED3_PB2.1@1109,1017
  Bottom Layer w15: v2(-76,-1194) -72.21,-1194 -67.33,-1189.12 C14.2@-2.13,-1189.12 ; C14.2@-1,-1190.26 C14.2@-2.13,-1189.12 ; v2@43.88,-1189.12 C14.2@-2.13,-1189.12 ; v2(44,-1189) v3(152.77,-1189) 212,-1189 220,-1181 R22.2@220,-1140.95 ; v3(263.28,-1140.95) R22.2@220,-1140.95 ; v3(448.35,-1019.84) 445.13,-1016.62 194.38,-1016.62 169,-1042 169,-1093.24 209.76,-1134 R22.2@220,-1134 R22.2@220,-1140.95 ; v2@1099.38,-1188.38 v3@1206.36,-1188.38 ; v3(1206.88,-1188.91) 1208.15,-1188.91 1210.49,-1186.57 1211.09,-1186.57 1235.58,-1162.08 ; 1233.72,-1162.08 1235.58,-1162.08 ; v2(1429,-1164) 1427.08,-1162.08 1235.58,-1162.08
  Bottom Layer w20: J1.1@345,-869.87 345,-767.54 366.72,-745.83 366.72,-686.96 ; 366.72,-650.43 366.72,-686.96 ; v1(498.87,-687.15) 366.91,-687.15 366.72,-686.96 ; v1@641.77,-718.85 643,-720.08 643,-720.2 674.3,-751.5 845.32,-751.5 CN3.1@948.26,-854.44 1131.56,-854.44 JP2.1@1142,-864.87 1142,-790.39 ; JP3.2@730,851 733.91,847.09 733.91,755.91 ; CN1.1@947.94,-1110.06 CN3.1@947.94,-854.76 ; CN1.1@951.04,-1105.74 972.46,-1124 1215.9,-1124 1233.72,-1141.82 1233.72,-1162.08 ; v1(1000,1248) 1000,1016 ; v1@1068,1016 1000,1016 ; 1152.64,-790.39 1142,-790.39 ; 733.91,755.91 361.02,383.02 361.02,-9.41 1142,-790.39 ; 733.91,755.91 832.91,755.91 1000,923 1000,1016
  other v1: 641,-717
TVDD*: JP1.2 R33.1 | length 129
  Top Layer w20: JP1.2@164,-1464 168.73,-1464 231.08,-1526.35 231.08,-1562.48
TVDD_DISCHARGE_EN: R18.2 U15.25 | length 404.9
  Top Layer w6: R18.2@230.53,-1709.22 277.51,-1709.22 296.48,-1690.25 296.48,-1633.45 363.58,-1566.34 432.61,-1566.34 472,-1605.73 U15.25@526.68,-1605.73
USB_DM: R10.2 U15.32 | length 536.9
  Top Layer w6: R10.2@79,-1959 135.4,-1902.6 287.28,-1902.6 446.36,-1743.53 U15.32@526.68,-1743.53
USB_DP: R11.2 U15.33 | length 471.3
  Top Layer w6: R11.2@136.5,-1959 173.45,-1922.05 300.73,-1922.05 459.56,-1763.21 U15.33@526.68,-1763.21
VBUS_PYLK: FUSE1.1 U6.5 USB1.A4 USB1.A9 USB1.B4 USB1.B9 | length 748.3
  Top Layer w10: USB1.A4@603.81,-2184.11 USB1.B9@615.62,-2184.11 ; USB1.B4@792.78,-2184.12 USB1.A9@804.6,-2184.12
  Top Layer w20: U6.5@397.15,-2184 397.98,-2184.83 438.58,-2184.83 v2(439.2,-2185.45) ; USB1.B9@610.05,-2166.44 v4@610.05,-2122.55 ; USB1.A9@798.87,-2164.14 v4@798.87,-2130.33
  Bottom Layer w15: 408.39,-2068.61 FUSE1.1@378,-2068.61 387,-2077.61 387,-2097 439.2,-2149.2 v2(439.2,-2185.45)
  Bottom Layer w20: v4@806.13,-2121.99 v4(806.62,-2121.5)
  Bottom Layer w30: FUSE1.1@378,-2068.61 FUSE1.1@386.66,-2059.94 ; 408.39,-2068.61 556.11,-2068.61 v4(609,-2121.5) ; v4@609.49,-2121.99 754.68,-2121.99 ; 754.68,-2120.59 v4@805.72,-2120.59
VCCA: C30.2 C42.1 CN4.13 L1.2 U18.13 | length 1059
  Top Layer w8: U18.13@817.58,13.63 817.58,-38.05 904.53,-125 1354.72,-125 1380.71,-150.99 1474.14,-150.99 1525.14,-100 CN4.13@1535,-100
  Top Layer w10: U18.13@817.58,13.63 817.58,92.63 v1(819.18,94.23)
  Bottom Layer w15: v1(819.18,94.23) 819.18,124.35 C30.2@815.94,127.58 815.51,128.01 C42.1@815.51,177.65 815.63,177.53 L1.2@871.29,177.53
VDD: C26.1 C32.2 C33.2 CN4.32 CN5.1 JP2.2 L1.1 R58.2 U18.32 U18.64 | length 3902.2
  Top Layer w10: CN5.1@0,-700 40.14,-700 329.55,-410.59 329.55,-211.47 472.86,-68.17 C32.2@472.86,-27.2 472.86,92.36 U18.64@502.63,92.36
  Top Layer w15: C32.2@473.22,-26.83 523.15,-26.83 v1(523.93,-26.05)
  Top Layer w20: U18.32@929.27,392.19 986.29,392.19 1026.69,432.59 1026.69,483.77 C26.1@1024.22,486.24 v1(1024.22,526.17) 1298.05,800 CN4.32@1435,800
  Bottom Layer w20: v1(523.93,-26.05) 1022.79,-26.05 1024.22,-27.48 ; L1.1@934.28,177.53 1024.22,177.53 ; v1(1024.22,526.17) 1024.22,177.53 ; 1212.64,-790.39 1204.62,-782.38 1204.62,-689.84 1204.62,-207.88 1024.22,-27.48 ; 1220.52,-782.52 1229.76,-791.76 1229.76,-841.81 1242,-854.05 JP2.2@1242,-864.87 ; 1024.22,-27.48 1024.22,177.53
VSSA: C30.1 C42.2 CN4.12 R60.1 U18.12 | length 1008.8
  Top Layer w8: v1(763.81,92.61) 766.73,92.61 797.9,61.44 797.9,-40.99 907.65,-150.74 1055.5,-150.74 1057,-152.24 ; 1057,-150.74 1346.13,-150.74 1385.68,-190.3 1425.3,-190.3 CN4.12@1435,-200
  Bottom Layer w15: 687.63,176.15 752.01,176.15 C42.2@753.51,177.65 753.51,128.01 C30.1@753.94,127.58 763.81,117.71 v1(763.81,92.61)
pads on no net: U15.42 U15.45 U21. U21.A8 U21.B8 USB1. USB1.A8 USB1.B8

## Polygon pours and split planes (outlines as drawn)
GND on Bottom Layer "NONET_L-01_P-001" (solid, remove dead copper, pour order 3): -165.87,1431.12 1599,1431.12 1599,-2494 -174.49,-2494
GND on Top Layer "NONET_L-01_P-001" (solid, remove dead copper, pour order 4): -165.87,1431.12 1599,1431.12 1599,-2494 -174.49,-2494

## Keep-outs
Keep-Out Layer:
  lines w8: -171,-2415.26 ccw(c-92.26,-2415.26) -92.26,-2494 1521.91,-2494 ccw(c1521.91,-2415.26) 1600.65,-2415.26 1600.65,-1020.65 ccw(c1559,-1020.65) 1559,-979 1459,-979 cw(c1486.5,-951.5) 1459,-924 1559,-924 ccw(c1559,-882.35) 1600.65,-882.35 1600.65,1361.75 1600.65,1381.12 ccw(c1550.65,1381.12) 1550.65,1431.12 1521.91,1431.12 -92.26,1431.12 -121,1431.12 ccw(c-121,1381.12) -171,1381.12 -171,1365.09 -171,-879 ccw(c-127.25,-880.25) -128.5,-924 -28.5,-924 cw(c-56,-951.5) -28.5,-979 -128.5,-979 ccw(c-127.25,-1022.75) -171,-1024 -171,-2415.26 ; 44,-979 cw(c71.5,-951.5) 44,-924 394,-924 414,-924 cw(c386.5,-951.5) 414,-979 394,-979 44,-979 ; 1089,-979 cw(c1116.5,-951.5) 1089,-924 1109,-924 1389,-924 cw(c1361.5,-951.5) 1389,-979 1109,-979 1089,-979

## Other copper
Top Layer:
  region net 3.3V_OUT: 234,933 289,933 295,927 295,871 285,861 236,861 227,870 227,926
  pour cut-out: 1484,-1124 1494,-1124 1494,-1134 1484,-1134
  pour cut-out: 104,-2004 114,-2004 114,-2014 104,-2014
  pour cut-out: 104,-1969 114,-1969 114,-1979 104,-1979
  pour cut-out: 159,-1969 164.5,-1969 164.5,-1991 159,-1991
  pour cut-out: 159,-2004 169,-2004 169,-2014 159,-2014
  region net 5V_USB_CHGR: 214,-2259 224,-2249 249,-2249 294,-2294 339,-2294 359,-2314 489,-2314 489,-2374 344,-2374 344,-2354 319,-2329 264,-2329 229,-2294 214,-2279
  region net 3V3_PYLK: 69,-2179 119,-2179 139,-2199 184,-2199 189,-2204 189,-2244 174,-2259 174,-2329 191.5,-2346.5 184,-2354 122.39,-2354 122.39,-2340.51 134,-2328.9 134,-2264 109,-2239 69,-2239
  region net 3V3_PYLK: 924,-2339 934,-2329 954,-2329 964,-2339 964,-2364 969,-2369 1014,-2369 1019,-2374 1019,-2389 1014,-2394 959,-2394 924,-2359
  region net 3V3_USB_PYLK: 1056.5,-2374 1129,-2374 1144,-2359 1164,-2359 1174,-2369 1174,-2389 1159,-2404 1144,-2404 1119,-2429 1119,-2469 1054,-2469 1054,-2375.67
  pour cut-out: 219,-1999 229,-1999 229,-2009 219,-2009
  pour cut-out: 274,-1999 284,-1999 284,-2009 274,-2009
  pour cut-out: 1456.43,-1457 1466.43,-1457 1466.43,-1467 1456.43,-1467
  pour cut-out: 1504,-1419 1514,-1419 1514,-1429 1504,-1429
Bottom Layer:
  region net 3.3V_OUT: 182,802 223,802 237,788 284,788 292,796 292,974 281,985 245,985 230,970 230,850 214,834 180,834 170,824 170,814
  region net NetC38_2: 351,909 351,934 356,939 432,939 484,991 484,1008 534,1008 541,1001 541,917 473,917 433,877 433,801 429,797 379,797 365,783 315,783 315,841 322,848 394,848 394,898 387,905 355,905

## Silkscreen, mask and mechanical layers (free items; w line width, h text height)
Top Overlay:
  drawing of 1057 lines, arcs and shapes, not listed
  text "USER_PB0" at -76,1071.64 h60
  text "NRST" at 1294,1071.64 h60
  text "VDD*" at 682.02,903 h50
  text "5V" at 809,902.53 h50
  text "3V3" at 581,900.58 h50
  text "33" at -120,863.58 h50
  text "34" at -17,863.58 h50
  text "31" at 1518,862.58 h50
  text "32" at 1417,860.58 h50
  text "VDD" at 1136.03,786.19 h55
  text "GND" at 1252.41,785.58 h55
  text "B13" at 206.35,784.63 h55
  text "B12" at 71,784 h55
  text "VDD_SEL" at 626.02,767.87 h50
  text "B11" at 1157,686.8 h55
  text "B10" at 1274.91,685.6 h55
  text "B14" at 71,684.4 h55
  text "B15" at 206.08,684.31 h55
  text "PY32F072-START V2.0" at 495,673.26 h65
  text "2025-03" at 675.94,588.54 h65
  text "B2" at 1157,587.41 h55
  text "B1" at 1308.87,586.2 h55
  text "C6" at 71,583.74 h55
  text "C7" at 219.77,583.5 h55
  text "B0" at 1157,487.44 h55
  text "C5" at 1297.93,485.73 h55
  text "C8" at 71,483.08 h55
  text "C9" at 219.7,482.7 h55
  text "C4" at 1157,386.98 h55
  text "A7" at 1298.44,386.45 h55
  text "A8" at 70.97,382.91 h55
  text "A9" at 219.93,382.37 h55
  text "A6" at 1156.97,287.01 h55
  text "A5" at 1298.16,286.59 h55
  text "A10" at 70.97,282.73 h55
  text "A11" at 209.48,282.63 h55
  text "A4" at 1156.97,187.75 h55
  text "F4" at 1305.39,187.32 h55
  text "A12" at 70.97,183.13 h55
  text "A13" at 202.7,182.26 h55
  text "F3" at 1157,87.72 h55
  text "A3" at 1298.44,87.28 h55
  text "F5" at 71,83.08 h55
  text "F6" at 229,81.58 h55
  text "A2" at 1156.97,-11.67 h55
  text "A1" at 1305.22,-12.12 h55
  text "A14" at 70.97,-16.51 h55
  text "A15" at 202.42,-18.39 h55
  text "A0" at 1135.97,-111.64 h55
  text "VCCA" at 1220.03,-112.59 h55
  text "C10" at 71,-117.17 h55
  text "C11" at 209.25,-119.19 h55
  text "VSSA" at 1136.03,-212.1 h55
  text "C3" at 1298.21,-213.11 h55
  text "C12" at 71,-217.83 h55
  text "F7" at 224.83,-218.81 h55
  text "C2" at 1156,-312.55 h55
  text "C1" at 1304.99,-313.57 h55
  text "B3" at 71,-318.06 h55
  text "B4" at 221.79,-318.42 h55
  text "C0" at 1156,-413.01 h55
  text "F2" at 1305.62,-412.98 h55
  text "B5" at 71,-418.11 h55
  text "B6" at 221.66,-418.74 h55
  text "F1" at 1160,-512 h55
  text "F0" at 1305.39,-512.96 h55
  text "B7" at 71,-517.58 h55
  text "F8" at 224.76,-519.06 h55
  text "C15" at 1147,-612.86 h55
  text "C14" at 1271.03,-613.43 h55
  text "B8" at 71,-617.76 h55
  text "B9" at 221.58,-619.39 h55
  text "C13" at 1147,-713.36 h55
  text "F9" at 1305.19,-713.42 h55
  text "GND" at 71,-718.42 h55
  text "VDD" at 187.03,-719 h55
  text "NRST" at 563.42,-786 h55 r90
  text "SWC" at 664.71,-786 h55 r90
  text "GND" at 766.01,-786 h55 r90
  text "SWD" at 867.31,-786 h55 r90
  text "VDD*" at 968,-785.97 h55 r90
  text "2" at 1422.95,-795 h50
  text "1" at 1525,-795 h50
  text "63" at -121,-796.47 h50
  text "64" at -23,-796.47 h50
  text "BOOT0" at 182,-810.78 h45
  text "GND" at 62,-814.02 h50
  text "VDD*" at 346.02,-814 h50
  text "VDD*" at 1096.02,-814.49 h45
  text "VDD" at 1205.02,-814.49 h45
  text "IDD" at 1297,-875 h45
  text "BOOT_SEL" at -85.37,-889.69 h40
  text "NRST" at 479,-1045.52 h45
  text "SWC" at 602.88,-1045.52 h45
  text "GND" at 711.55,-1045.52 h45
  text "SWD" at 814.91,-1045.52 h45
  text "VDD*" at 923.02,-1046 h45
  text "SWO" at 471,-1317.53 h55
  text "RTS" at 604,-1317.53 h55
  text "DTR" at 709,-1318.12 h55
  text "TX" at 825.31,-1318.12 h55
  text "RX" at 919,-1318.12 h55
  text "5V" at 19,-1418.36 h60
  text "3V3" at 239,-1418.31 h60
  text "VDD*" at 94.03,-1419 h60
  text "BT0" at 964.47,-2080 h50 r90
  text "VDD" at 1062.9,-2079.98 h50 r90
  text "DIO" at 1162.43,-2080 h50 r90
  text "GND" at 1261.95,-2080 h50 r90
  text "CLK" at 1361.47,-2080 h50 r90
  text "PY-LINK V2.0" at 526.04,-2096.72 h65
Bottom Overlay:
Mechanical 1:
  lines w6: 44,-979 394,-979 414,-979 ; 44,-924 394,-924 414,-924 ; 1089,-979 1109,-979 1389,-979 ; 1089,-924 1109,-924 1389,-924
  lines w8: 44,-979 cw(c71.5,-951.5) 44,-924 ; 414,-979 ccw(c386.5,-951.5) 414,-924 ; 1089,-979 cw(c1116.5,-951.5) 1089,-924 ; 1389,-979 ccw(c1361.5,-951.5) 1389,-924

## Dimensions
-128.5,-924 to -92.26,1431.12 on Mechanical 1
1599,-2494 to 1665,1432 on Mechanical 1
-92.26,-2494 to -176,-989 on Mechanical 1
-171,-2494 to 1599,-2554 on Mechanical 1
